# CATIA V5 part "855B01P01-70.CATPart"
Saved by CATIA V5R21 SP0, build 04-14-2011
Part number: 855B01P01-70
Bounding box of the stored display mesh (mm): x -76.5 to 76.5, y -25.54 to 25.54, z -76.557 to 6.5
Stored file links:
  C:\Users\ALI OZGUN\Desktop\alhan\855B01P01-70.CATPart
  Copy (1) of 845B01P21.CATPart
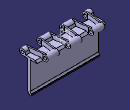
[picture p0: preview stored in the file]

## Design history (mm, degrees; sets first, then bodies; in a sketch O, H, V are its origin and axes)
Body1 (main body)
  Sketch1 on yz-plane, origin (0, 0, 0), H (0, 1, 0), V (0, 0, 1)
    construction line L1 (-19.05, 0) -> (19.05, 0)
    point P1 (-19.05, 0)
    point P2 (19.05, 0)
    line L2 (-19.05, 6.5) -> (19.05, 6.5)
    line L3 (19.05, -6.5) -> (-19.05, -6.5)
    arc A1 centre (19.05, 0) radius 6.5 from (19.05, 6.5) to (19.05, -6.5) cw
    arc A2 centre (-19.05, 0) radius 6.5 from (-19.05, -6.5) to (-19.05, 6.5) cw
    circle A3 centre (19.05, 0) radius 3.25
    circle A4 centre (-19.05, 0) radius 3.25
    distance L1 L2 = 6.5
    length L1 = 38.1
    distance P2 V = 19.05
    radius A3 = 3.25
    radius A4 = 3.25
    coincidence: P1 H
    horizontal: L1 H
    tangency: A1 L2, A2 L2, A1 L3, A2 L3
  Pad1: profile Sketch1, direction (1, 0, 0), length 76.5, mirrored extent
  Sketch2 on face of Pad1 from Sketch1.L2, origin (0, 0, 6.5), H (1, 0, 0), V (0, 1, 0)
    line L1 (38, -14) -> (64, -14)
    line L2 (64, -14) -> (64, -36.0786)
    line L3 (64, -36.0786) -> (38, -36.0786)
    line L4 (38, -36.0786) -> (38, -14)
    line L5 (-13, -14) -> (13, -14)
    line L6 (13, -14) -> (13, -36.0786)
    line L7 (13, -36.0786) -> (-13, -36.0786)
    line L8 (-13, -36.0786) -> (-13, -14)
    point P7 (13, -36.0786)
    line L9 (-64, -14) -> (-38, -14)
    line L10 (-38, -14) -> (-38, -32.269)
    line L11 (-38, -32.269) -> (-64, -32.269)
    line L12 (-64, -32.269) -> (-64, -14)
    line L13 (85.7823, 31.3847) -> (63.5, 31.3847)
    line L14 (63.5, 31.3847) -> (63.5, 14)
    line L15 (63.5, 14) -> (85.7823, 14)
    line L16 (85.7823, 14) -> (85.7823, 31.3847)
    point P17 (12.5, 31.3847)
    line L17 (12.5, 31.3847) -> (38.5, 31.3847)
    line L18 (38.5, 31.3847) -> (38.5, 14)
    line L19 (38.5, 14) -> (12.5, 14)
    line L20 (12.5, 14) -> (12.5, 31.3847)
    point P19 (38.5, 14)
    line L21 (-38.5, 32.0801) -> (-12.5, 32.0801)
    line L22 (-12.5, 32.0801) -> (-12.5, 14)
    line L23 (-12.5, 14) -> (-38.5, 14)
    line L24 (-38.5, 14) -> (-38.5, 32.0801)
    point P23 (-12.5, 14)
    line L25 (-81.4786, 33.8185) -> (-63.5, 33.8185)
    line L26 (-63.5, 33.8185) -> (-63.5, 14)
    line L27 (-63.5, 14) -> (-81.4786, 14)
    line L28 (-81.4786, 14) -> (-81.4786, 33.8185)
    point P27 (-63.5, 14)
    reference projected line E1 (76.5, 19.05) -> (76.5, -19.05) from edge [face of Pad1 from Sketch1.L2 | end face of Pad1]
    reference projected line E2 (-76.5, 19.05) -> (-76.5, -19.05) from edge [start face of Pad1 | face of Pad1 from Sketch1.L2]
    reference projected line E3 (-76.5, 19.05) -> (-76.5, -19.05) from edge [start face of Pad1 | face of Pad1 from Sketch1.L2]
    reference projected line E4 (76.5, 19.05) -> (76.5, -19.05) from edge [face of Pad1 from Sketch1.L2 | end face of Pad1]
    distance L14 E1 = 13
    distance L26 E2 = 13
    distance L12 E3 = 12.5
    distance L2 E4 = 12.5
    distance L23 L5 = 28
    distance L5 H = 14
    distance L4 L2 = 26
    distance L12 L10 = 26
    distance L10 L8 = 25
    distance L6 L4 = 25
    distance L24 L26 = 25
    distance L18 L14 = 25
    distance L26 L22 = 51
    distance L20 L18 = 26
    horizontal: L1 H, L3 H, L5 H, L7 H, L9 H, L11 H, L13 H, L15 H, L17 H, L19 H, L21 H, L23 H, L25 H, L27 H
    vertical: L2 V, L4 V, L6 V, L8 V, L10 V, L12 V, L14 V, L16 V, L18 V, L20 V, L22 V, L24 V, L26 V, L28 V
    coincidence: P7 L3, P17 L13, P19 L15, P23 L15, P27 L15, L1 L5, L9 L5
  Pocket1: profile Sketch2, direction (0, 0, -1), length 53.5
  Sketch3 on end face of Pad1, origin (76.5, 0, 0), H (0, 1, 0), V (0, 0, 1)
    projected arc E1 centre (19.05, 0) radius 6.5 from (19.05, -6.5) to (19.05, 6.5) ccw from edge [face of Pocket1 from Sketch2.L14 | face of Pad1 from Sketch1.A1]
    projected arc E2 centre (19.05, 0) radius 6.5 from (19.05, -6.5) to (13.0358, 2.4657) ccw from edge [face of Pocket1 from Sketch2.L14 | face of Pad1 from Sketch1.A1]
    point P1 (19.05, -6.5)
    projected arc E3 centre (-19.05, 0) radius 6.5 from (-19.05, 6.5) to (-19.05, -6.5) ccw from edge [face of Pad1 from Sketch1.A2 | end face of Pad1]
    projected arc E4 centre (-19.05, 0) radius 6.5 from (-13.0358, 2.4657) to (-19.05, -6.5) ccw from edge [face of Pad1 from Sketch1.A2 | end face of Pad1]
    point P4 (-19.05, -6.5)
    projected line E5 (-19.05, -6.5) -> (14, -6.5) from edge [face of Pad1 from Sketch1.L3 | end face of Pad1]
    point P5 (-19.05, -6.5)
    projected line E6 (19.05, -6.5) -> (14, -6.5) from edge [face of Pocket1 from Sketch2.L14 | face of Pad1 from Sketch1.L3]
    point P7 (19.05, -6.5)
    line L1 (-13.0358, 2.4657) -> (-11, -2.5)
    line L2 (-11, -2.5) -> (11, -2.5)
    point P10 (11, -2.5)
    line L3 (11, -2.5) -> (13.0358, 2.4657)
    distance L2 E5 = 4
    length L2 = 22
    distance P10 V = 11
    horizontal: L2 H
    tangency: L3 E1, L1 E3
    coincidence: P1 P7, P4 P5
  Pocket2: profile Sketch3, direction (-1, 0, 0), length 172.5, outer side
  Sketch4 on face of Pocket2 from Sketch3.L2, origin (0, 0, -2.5), H (1, 0, 0), V (0, 1, 0)
    projected line E1 (38, -14) -> (38, -25.55) from edge [face of Pocket2 | face of Pocket1 from Sketch2.L4]
    projected line E2 (38, -14) -> (38, -19.05) from edge [face of Pocket2 | face of Pocket1 from Sketch2.L4]
    point P1 (38, -14)
    point P2 (38, -25.55)
    projected line E3 (13, -25.55) -> (13, -14) from edge [face of Pocket2 | face of Pocket1 from Sketch2.L6]
    projected line E4 (13, -19.05) -> (13, -14) from edge [face of Pocket2 | face of Pocket1 from Sketch2.L6]
    point P3 (13, -25.55)
    point P4 (13, -14)
    projected line E5 (64, -25.55) -> (64, -14) from edge [face of Pocket2 | face of Pocket1 from Sketch2.L2]
    projected line E6 (64, -19.05) -> (64, -14) from edge [face of Pocket2 | face of Pocket1 from Sketch2.L2]
    point P5 (64, -25.55)
    point P6 (64, -14)
    projected line E7 (38.5, 14) -> (38.5, 25.55) from edge [face of Pocket2 | face of Pocket1 from Sketch2.L18]
    projected line E8 (38.5, 14) -> (38.5, 19.05) from edge [face of Pocket2 | face of Pocket1 from Sketch2.L18]
    point P7 (38.5, 14)
    point P8 (38.5, 25.55)
    projected line E9 (63.5, 14) -> (63.5, 25.55) from edge [face of Pocket1 from Sketch2.L14 | face of Pocket2]
    projected line E10 (63.5, 14) -> (63.5, 19.05) from edge [face of Pocket1 from Sketch2.L14 | face of Pocket2]
    point P9 (63.5, 14)
    point P10 (63.5, 25.55)
    projected line E11 (12.5, 25.55) -> (12.5, 14) from edge [face of Pocket2 | face of Pocket1 from Sketch2.L20]
    projected line E12 (12.5, 19.05) -> (12.5, 14) from edge [face of Pocket2 | face of Pocket1 from Sketch2.L20]
    point P11 (12.5, 25.55)
    point P12 (12.5, 14)
    offset line E13 (9.5, 25.55) -> (9.5, 14) from edge [face of Pocket2 | face of Pocket1 from Sketch2.L20]
    offset line E14 (9.5, 19.05) -> (9.5, 14) from edge [face of Pocket2 | face of Pocket1 from Sketch2.L20]
    point P13 (9.5, 25.55)
    point P14 (9.5, 14)
    offset line E15 (16, -25.55) -> (16, -14) from edge [face of Pocket2 | face of Pocket1 from Sketch2.L6]
    offset line E16 (16, -19.05) -> (16, -14) from edge [face of Pocket2 | face of Pocket1 from Sketch2.L6]
    point P15 (16, -25.55)
    point P16 (16, -14)
    offset line E17 (35, -14) -> (35, -25.55) from edge [face of Pocket2 | face of Pocket1 from Sketch2.L4]
    offset line E18 (35, -14) -> (35, -19.05) from edge [face of Pocket2 | face of Pocket1 from Sketch2.L4]
    point P17 (35, -14)
    point P18 (35, -25.55)
    offset line E19 (41.5, 14) -> (41.5, 25.55) from edge [face of Pocket2 | face of Pocket1 from Sketch2.L18]
    offset line E20 (41.5, 14) -> (41.5, 19.05) from edge [face of Pocket2 | face of Pocket1 from Sketch2.L18]
    point P19 (41.5, 14)
    point P20 (41.5, 25.55)
    offset line E21 (60.5, 14) -> (60.5, 25.55) from edge [face of Pocket1 from Sketch2.L14 | face of Pocket2]
    offset line E22 (60.5, 14) -> (60.5, 19.05) from edge [face of Pocket1 from Sketch2.L14 | face of Pocket2]
    point P21 (60.5, 14)
    point P22 (60.5, 25.55)
    offset line E23 (67, -25.55) -> (67, -14) from edge [face of Pocket2 | face of Pocket1 from Sketch2.L2]
    offset line E24 (67, -19.05) -> (67, -14) from edge [face of Pocket2 | face of Pocket1 from Sketch2.L2]
    point P23 (67, -25.55)
    point P24 (67, -14)
    line L1 (13, -14) -> (9.5, 14)
    line L2 (16, -14) -> (12.5, 14)
    line L3 (35, -14) -> (38.5, 14)
    line L4 (38, -14) -> (41.5, 14)
    line L5 (64, -14) -> (60.5, 14)
    line L6 (67, -14) -> (63.5, 14)
    projected line E25 through (0, -19.05) direction (1, 0) from axis of face of Pocket2
    projected line E26 (13, -19.05) -> (16, -19.05) from axis of face of Pocket2
    projected line E27 (64, -19.05) -> (67, -19.05) from axis of face of Pocket2
    projected line E28 (35, -19.05) -> (38, -19.05) from axis of face of Pocket2
    point P25 (-10000000, -19.05)
    point P26 (10000000, -19.05)
    point P27 (67, -19.05)
    point P28 (38, -19.05)
    point P29 (64, -19.05)
    point P30 (64, -19.05)
    point P31 (38, -19.05)
    point P32 (35, -19.05)
    point P33 (16, -19.05)
    point P34 (35, -19.05)
    point P35 (16, -19.05)
    point P36 (13, -19.05)
    point P37 (13, -19.05)
    projected line E29 through (0, 19.05) direction (1, 0) from axis of face of Pocket2
    projected line E30 (9.5, 19.05) -> (12.5, 19.05) from axis of face of Pocket2
    projected line E31 (38.5, 19.05) -> (41.5, 19.05) from axis of face of Pocket2
    projected line E32 (60.5, 19.05) -> (63.5, 19.05) from axis of face of Pocket2
    point P38 (-10000000, 19.05)
    point P39 (10000000, 19.05)
    point P40 (63.5, 19.05)
    point P41 (9.5, 19.05)
    point P42 (9.5, 19.05)
    point P43 (12.5, 19.05)
    point P44 (12.5, 19.05)
    point P45 (38.5, 19.05)
    point P46 (38.5, 19.05)
    point P47 (41.5, 19.05)
    point P48 (60.5, 19.05)
    point P49 (41.5, 19.05)
    point P50 (60.5, 19.05)
    point P51 (-10000000, -19.05)
    point P52 (10000000, -19.05)
    point P53 (-10000000, 19.05)
    point P54 (10000000, 19.05)
    construction line L7 through (0, -19.05) direction (-1, 0)
    construction line L8 through (0, 19.05) direction (-1, 0)
    point P55 (-10000000, -19.05)
    point P56 (10000000, -19.05)
    point P57 (-16, -19.05)
    point P58 (-13, -19.05)
    point P59 (-67, -19.05)
    point P60 (-64, -19.05)
    point P61 (-38, -19.05)
    point P62 (-35, -19.05)
    point P63 (-38, -25.55)
    point P64 (-38, -14)
    point P65 (-38, -19.05)
    point P66 (-13, -14)
    point P67 (-13, -25.55)
    point P68 (-13, -19.05)
    point P69 (-64, -14)
    point P70 (-64, -25.55)
    point P71 (-64, -19.05)
    point P72 (-38.5, 25.55)
    point P73 (-38.5, 14)
    point P74 (-38.5, 19.05)
    point P75 (-63.5, 25.55)
    point P76 (-63.5, 14)
    point P77 (-63.5, 19.05)
    point P78 (-12.5, 14)
    point P79 (-12.5, 25.55)
    point P80 (-12.5, 19.05)
    point P81 (-9.5, 14)
    point P82 (-9.5, 25.55)
    point P83 (-9.5, 19.05)
    point P84 (-16, -14)
    point P85 (-16, -25.55)
    point P86 (-16, -19.05)
    point P87 (-35, -25.55)
    point P88 (-35, -14)
    point P89 (-35, -19.05)
    point P90 (-41.5, 25.55)
    point P91 (-41.5, 14)
    point P92 (-41.5, 19.05)
    point P93 (-60.5, 25.55)
    point P94 (-60.5, 14)
    point P95 (-60.5, 19.05)
    point P96 (-67, -14)
    point P97 (-67, -25.55)
    line L9 (-13, -14) -> (-9.5, 14)
    line L10 (-16, -14) -> (-12.5, 14)
    line L11 (-35, -14) -> (-38.5, 14)
    line L12 (-38, -14) -> (-41.5, 14)
    line L13 (-64, -14) -> (-60.5, 14)
    line L14 (-67, -14) -> (-63.5, 14)
    point P98 (-10000000, 19.05)
    point P99 (10000000, 19.05)
    point P100 (-12.5, 19.05)
    point P101 (-9.5, 19.05)
    point P102 (-41.5, 19.05)
    point P103 (-38.5, 19.05)
    point P104 (-60.5, 19.05)
    construction line L15 through (0, -19.05) direction (-1, 0)
    line L16 (-13, -19.05) -> (-16, -19.05)
    line L17 (-64, -19.05) -> (-67, -19.05)
    line L18 (-35, -19.05) -> (-38, -19.05)
    construction line L19 (-38, -14) -> (-38, -25.55)
    line L20 (-38, -14) -> (-38, -19.05)
    construction line L21 (-13, -25.55) -> (-13, -14)
    line L22 (-13, -19.05) -> (-13, -14)
    construction line L23 (-64, -25.55) -> (-64, -14)
    line L24 (-64, -19.05) -> (-64, -14)
    construction line L25 (-38.5, 14) -> (-38.5, 25.55)
    line L26 (-38.5, 14) -> (-38.5, 19.05)
    construction line L27 (-63.5, 14) -> (-63.5, 25.55)
    line L28 (-63.5, 14) -> (-63.5, 19.05)
    construction line L29 (-12.5, 25.55) -> (-12.5, 14)
    line L30 (-12.5, 19.05) -> (-12.5, 14)
    construction line L31 (-9.5, 25.55) -> (-9.5, 14)
    line L32 (-9.5, 19.05) -> (-9.5, 14)
    construction line L33 (-16, -25.55) -> (-16, -14)
    line L34 (-16, -19.05) -> (-16, -14)
    construction line L35 (-35, -14) -> (-35, -25.55)
    line L36 (-35, -14) -> (-35, -19.05)
    construction line L37 (-41.5, 14) -> (-41.5, 25.55)
    line L38 (-41.5, 14) -> (-41.5, 19.05)
    construction line L39 (-60.5, 14) -> (-60.5, 25.55)
    line L40 (-60.5, 14) -> (-60.5, 19.05)
    construction line L41 (-67, -25.55) -> (-67, -14)
    line L42 (-67, -19.05) -> (-67, -14)
    construction line L43 through (0, 19.05) direction (-1, 0)
    line L44 (-9.5, 19.05) -> (-12.5, 19.05)
    line L45 (-38.5, 19.05) -> (-41.5, 19.05)
    line L46 (-60.5, 19.05) -> (-63.5, 19.05)
    parallelism: L2 L1, L4 L3
    coincidence: E1 P28, E5 P29, E25 P30, E25 P31, E25 P32, E15 P33, E17 P34, E25 P35, E25 P36, E3 P37, E13 P41, E29 P42, E29 P43, E11 P44, E7 P45, E29 P46, E29 P47, E29 P48, E19 P49, E21 P50, P28 P31, P29 P30, P32 P34, P33 P35, P36 P37, P41 P42, P43 P44, P45 P46, P47 P49, P48 P50
    symmetry: P26 P51 V, P25 P52 V, E25 L7 V, P39 P53 V, P38 P54 V, E29 L8 V, P26 P55 V, P25 P56 V, P33 P57 V, P37 P58 V, P27 P59 V, P29 P60 V, P28 P61 V, P34 P62 V, E25 L15 V, P2 P63 V, P1 P64 V, P31 P65 V, E1 L19 V, P4 P66 V, P3 P67 V, P36 P68 V, E3 L21 V, P6 P69 V, P5 P70 V, P30 P71 V, E5 L23 V, P8 P72 V, P7 P73 V, P46 P74 V, E7 L25 V, P10 P75 V, P9 P76 V, P40 P77 V, E9 L27 V, P12 P78 V, P11 P79 V, P43 P80 V, E11 L29 V, P14 P81 V, P13 P82 V, P42 P83 V, E13 L31 V, P16 P84 V, P15 P85 V, P35 P86 V, E15 L33 V, P18 P87 V, P17 P88 V, P32 P89 V, E17 L35 V, P20 P90 V, P19 P91 V, P47 P92 V, E19 L37 V, P22 P93 V, P21 P94 V, P48 P95 V, E21 L39 V, P24 P96 V, P23 P97 V, E23 L41 V, L1 L9 V, L2 L10 V, L3 L11 V, L4 L12 V, L5 L13 V, L6 L14 V, P39 P98 V, P38 P99 V, P44 P100 V, P41 P101 V, P49 P102 V, P45 P103 V, P50 P104 V, E29 L43 V, E25 L18 V, E25 L17 V, E25 L16 V, E1 L20 V, E3 L22 V, E5 L24 V, E7 L26 V, E9 L28 V, E11 L30 V, E13 L32 V, E15 L34 V, E17 L36 V, E19 L38 V, E21 L40 V, E23 L42 V, E29 L46 V, E29 L45 V, E29 L44 V
  Pad2: profile Sketch4, direction (0, 0, 1), length 9
  Sketch5 on yz-plane, origin (0, 0, 0), H (0, 1, 0), V (0, 0, 1)
    projected circle E1 centre (-19.05, 0) radius 3.25 from edge [end face of Pad1 | face of Pad1 from Sketch1.A4]
    circle A1 centre (19.05, 0) radius 3.25
    reference projected circle E2 centre (19.05, 0) radius 3.25 from edge [face of Pad1 from Sketch1.A3 | face of Pad2]
    coincidence: A1 E2
  Pocket3: profile Sketch5, direction (-1, 0, 0), length 95, mirrored extent
  RemoveFace1: RemoveFaces (face of Pocket2 from Sketch3.L3; face of Pocket2; face of Pocket2 from Sketch3.L3; face of Pocket2; face of Pocket2 from Sketch3.L1; face of Pocket2; face of Pocket2 from Sketch3.L1; face of Pocket2; face of Pocket2; face of Pocket2; face of Pocket2; face of Pocket2 from Sketch3.L3; face of Pocket2 from Sketch3.L3; face of Pocket2 from Sketch3.L1)
  Chamfer1: length 4, angle 45, on edge [face of Pocket1 from Sketch2.L27 | face of Pocket2 from Sketch3.L2]; edge [face of Pocket1 from Sketch2.L9 | face of Pocket2 from Sketch3.L2]; edge [face of Pocket1 from Sketch2.L19 | face of Pocket2 from Sketch3.L2]; edge [face of Pocket1 from Sketch2.L5 | face of Pocket2 from Sketch3.L2]; edge [face of Pocket1 from Sketch2.L1 | face of Pocket2 from Sketch3.L2]; edge [face of Pocket1 from Sketch2.L15 | face of Pocket2 from Sketch3.L2]; edge [face of Pocket1 from Sketch2.L23 | face of Pocket2 from Sketch3.L2]
  Sketch6 on yz-plane, origin (0, 0, 0), H (0, 1, 0), V (0, 0, 1)
    point P1 (-4.05, -6.5)
    line L1 (-4.05, -6.5) -> (-4.05, -67.8504)
    arc A1 centre (2.9349, -67.8504) radius 6.9849 from (-4.05, -67.8504) to (0.7968, -74.5) ccw
    point P4 (0.7968, -74.5)
    reference projected point E1 (-19.05, 0) from axis of face of Pocket2
    reference intersected line E2 (19.05, -6.5) -> (-19.05, -6.5) from face of Pocket2
    reference projected line E3 (-19.05, -6.5) -> (19.05, -6.5) from edge [face of Pocket2 | end face of Pad1]
    distance L1 E1 = 15
    distance P4 E2 = 68
    vertical: L1 V
    tangency: A1 L1
    coincidence: P1 E3
  Pad3: profile Sketch6, direction (1, 0, 0), up to end face of Pad1, opposite side up to start face of Pad1, thin wall 5
  Fillet1: radius 1, on edge [face of Pad3 | face of Pad3] (x2)
Body2
  Solid1: linked copy from another document
  Translate1: Direction zx-plane, Length 38.1, ToTransfor Solid1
